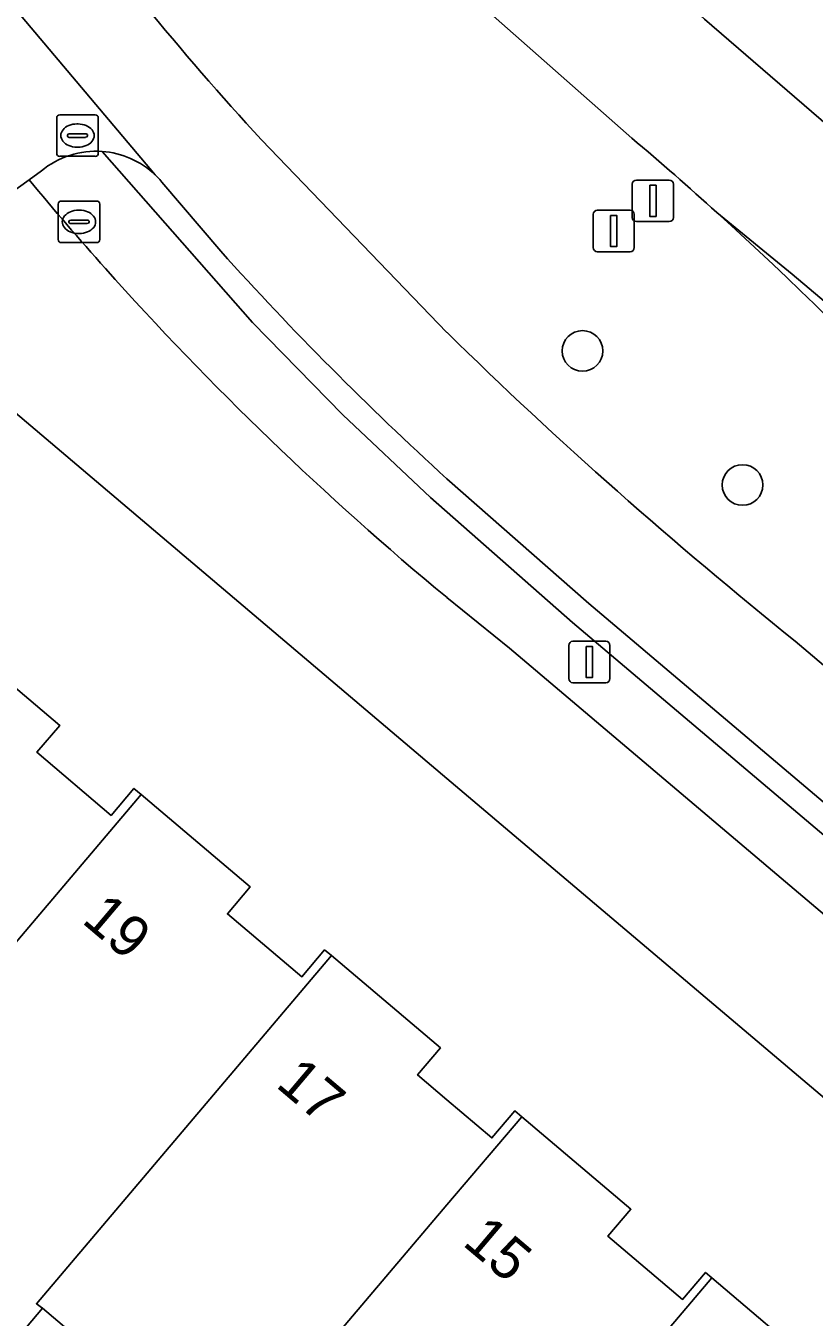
# Model space of a CAD drawing. Extents: x 156412 to 157779, y 382335 to 383768.
# Drawn here: x 156989.86 to 157008.84, y 382838.16 to 382869.24 of the extents above; entities that cross this region are included whole.
import ezdxf

# ---------------------------------------------------------------- set-up
doc = ezdxf.new("R2010")
doc.units = 0
for name, color, linetype in [('IMGEO_Berm_groen', 7, 'Continuous'), ('IMGEO_Boom', 7, 'Continuous'), ('IMGEO_Erf', 7, 'Continuous'), ('IMGEO_Fietspad_gesloten', 7, 'Continuous'), ('IMGEO_Groenvoorziening', 7, 'Continuous'), ('IMGEO_Haag', 7, 'Continuous'), ('IMGEO_Lichtmast', 7, 'Continuous'), ('IMGEO_Pand', 7, 'Continuous'), ('IMGEO_Pand_nummerreeks', 7, 'Continuous'), ('IMGEO_Rijbaan_regionaal_gesloten', 7, 'Continuous'), ('IMGEO_Rioolput', 7, 'Continuous'), ('IMGEO_Verkeersbordpaal', 7, 'Continuous'), ('IMGEO_Voetpad_open', 7, 'Continuous')]:
    doc.layers.add(name, color=color, linetype=linetype)

msp = doc.modelspace()

# ---------------------------------------------------------------- linework, layer by layer
at = {"layer": 'IMGEO_Berm_groen'}
for points in [[(157004.449, 382866.535), (157000.639, 382869.902)], [(156995.532, 382866.494), (157000, 382861.855)], [(157003.022, 382854.879), (156999.599, 382857.889), (156997.496, 382859.874), (156995.317, 382862.098), (156991.703, 382866.215)], [(156990.239, 382865.747), (156989.942, 382865.533)], [(157000, 382855.475), (157001.505, 382854.26), (157026.185, 382833.362), (157021.741, 382839.034), (157003.022, 382854.879)], [(157008.381, 382854.428), (157029.109, 382836.876), (157023.909, 382845.783)]]:
    msp.add_lwpolyline(points, dxfattribs=at)
for centre, radius, start, end in [((157052.723, 382918.878), 77.555, 209.71967, 222.48797), ((156951.788, 382804.343), 81.493, 47.83263, 49.74397), ((156991.556, 382864.151), 2.069, 85.925, 129.5303), ((157046.521, 382912.357), 73.441, 219.61068, 221.80815), ((156949.459, 382801.656), 85.048, 37.97711, 47.88442), ((157048.582, 382914.11), 76.146, 221.75797, 230.35703), ((157079.4, 382943.011), 113.537, 225.62684, 231.28029)]:
    msp.add_arc(centre, radius, start, end, dxfattribs=at)
at = {"layer": 'IMGEO_Boom'}
for centre in [(157003.261, 382861.414), (157007.113, 382858.187)]:
    msp.add_circle(centre, 0.489, dxfattribs=at)
at = {"layer": 'IMGEO_Erf'}
msp.add_lwpolyline([(157000, 382851.126), (156988.027, 382861.266), (156983.836, 382860.322), (156945.662, 382851.459), (156966.822, 382759.288), (156968.984, 382750), (156976.601, 382717.276), (157000, 382744.884), (157004.336, 382750), (157004.803, 382750.551), (157041.321, 382793.644), (157052.477, 382806.707), (157037.953, 382818.984), (157034.372, 382822.017), (157032.691, 382823.44)], close=True, dxfattribs=at)
for points in [[(156988.066, 382854.616), (156990.682, 382852.401), (156990.132, 382851.753), (156991.917, 382850.235), (156992.466, 382850.883), (156992.642, 382850.735), (156995.264, 382848.511), (156994.714, 382847.863), (156996.507, 382846.349), (156997.056, 382846.998), (156997.221, 382846.858), (156999.843, 382844.638), (156999.294, 382843.989), (157000, 382843.389), (157001.081, 382842.471), (157001.63, 382843.12), (157001.798, 382842.978), (157004.424, 382840.754), (157003.874, 382840.105), (157005.67, 382838.585), (157006.221, 382839.233), (157006.377, 382839.1), (157008.997, 382836.873)], [(157011.713, 382817.561), (157006.989, 382821.57), (157008.283, 382823.095), (157004.004, 382826.72), (157002.709, 382825.196), (157000, 382827.497), (156997.834, 382829.337), (156999.12, 382830.85), (156994.703, 382834.611), (156990.265, 382838.372), (156988.973, 382836.846), (156984.103, 382840.969), (156985.39, 382842.489), (156981.86, 382845.483), (156978.289, 382841.269), (156976.092, 382838.674), (156974.35, 382840.15), (156976.547, 382842.745), (156978.826, 382845.436), (156974.937, 382848.74), (156976.048, 382850.048), (156969.215, 382848.468)]]:
    msp.add_lwpolyline(points, dxfattribs=at)
at = {"layer": 'IMGEO_Fietspad_gesloten'}
for points in [[(156992.974, 382865.655), (156988.864, 382870.528)], [(156988.864, 382870.528), (156992.974, 382865.655), (156993.032, 382865.598), (156993.087, 382865.539), (156993.14, 382865.477), (156994.554, 382863.812)], [(157000, 382861.855), (156995.532, 382866.494)], [(156988.655, 382864.607), (156989.942, 382865.533)], [(156989.942, 382865.533), (156990.239, 382865.747)], [(157000, 382858.335), (157003.414, 382855.333), (157019.915, 382841.365), (157038.617, 382825.406), (157038.906, 382825.171), (157041.277, 382823.243), (157041.521, 382822.993), (157053.712, 382810.538), (157053.424, 382809.597), (157055.088, 382808.988), (157054.971, 382808.492)], [(157057.235, 382812.195), (157055.114, 382814.174), (157048.576, 382819.923), (157045.729, 382822.419), (157042.831, 382825.236), (157040.215, 382827.472), (157029.109, 382836.876), (157008.381, 382854.428)]]:
    msp.add_lwpolyline(points, dxfattribs=at)
for centre, radius, start, end in [((157052.723, 382918.878), 77.555, 209.71967, 222.48797), ((156991.556, 382864.151), 2.069, 85.925, 129.5303), ((156991.554, 382864.154), 2.066, 46.5793, 85.8643), ((157052.844, 382916.326), 78.457, 222.01598, 227.65881), ((157079.4, 382943.011), 113.537, 225.62684, 231.28029)]:
    msp.add_arc(centre, radius, start, end, dxfattribs=at)
at = {"layer": 'IMGEO_Groenvoorziening'}
for points in [[(156991.703, 382866.215), (156995.317, 382862.098), (156997.496, 382859.874), (156999.599, 382857.889), (157003.022, 382854.879), (157021.741, 382839.034), (157019.915, 382841.365), (157003.414, 382855.333)], [(156994.554, 382863.812), (156993.14, 382865.477), (156993.087, 382865.539), (156993.032, 382865.598), (156992.974, 382865.655)], [(157003.414, 382855.333), (157000, 382858.335)]]:
    msp.add_lwpolyline(points, dxfattribs=at)
for centre, radius, start, end in [((156991.554, 382864.154), 2.066, 46.5793, 85.8643), ((157052.844, 382916.326), 78.457, 222.01598, 227.65881)]:
    msp.add_arc(centre, radius, start, end, dxfattribs=at)
at = {"layer": 'IMGEO_Haag'}
for points in [[(156991.703, 382866.215), (156995.317, 382862.098), (156997.496, 382859.874), (156999.599, 382857.889), (157003.022, 382854.879), (157021.741, 382839.034), (157019.915, 382841.365), (157003.414, 382855.333)], [(156994.554, 382863.812), (156993.14, 382865.477), (156993.087, 382865.539), (156993.032, 382865.598), (156992.974, 382865.655)], [(157003.414, 382855.333), (157000, 382858.335)]]:
    msp.add_lwpolyline(points, dxfattribs=at)
for centre, radius, start, end in [((156991.554, 382864.154), 2.066, 46.5793, 85.8643), ((157052.844, 382916.326), 78.457, 222.01598, 227.65881)]:
    msp.add_arc(centre, radius, start, end, dxfattribs=at)
at = {"layer": 'IMGEO_Lichtmast'}
for p, q in [((157003.031, 382854.426), (157003.821, 382854.426)), ((157003.821, 382854.426), (157003.031, 382854.426)), ((157002.931, 382853.526), (157002.931, 382854.326)), ((157002.931, 382854.326), (157002.931, 382853.526)), ((157003.921, 382854.326), (157003.921, 382853.526)), ((157003.921, 382853.526), (157003.921, 382854.326)), ((157003.821, 382853.426), (157003.031, 382853.426)), ((157003.031, 382853.426), (157003.821, 382853.426))]:
    msp.add_line(p, q, dxfattribs=at)
msp.add_lwpolyline([(157003.351, 382854.301), (157003.501, 382854.301), (157003.501, 382853.551), (157003.351, 382853.551), (157003.351, 382854.301)], dxfattribs=at)
for centre, start, end in [((157003.031, 382854.326), 90, 180), ((157003.031, 382854.326), 90, 180), ((157003.821, 382854.326), 0, 90), ((157003.821, 382854.326), 360, 90), ((157003.031, 382853.526), 180, 270), ((157003.031, 382853.526), 180, 270), ((157003.821, 382853.526), 270, 0), ((157003.821, 382853.526), 270, 0)]:
    msp.add_arc(centre, 0.1, start, end, dxfattribs=at)
at = {"layer": 'IMGEO_Pand'}
for points in [[(156992.642, 382850.735), (156992.466, 382850.883), (156991.917, 382850.235), (156990.132, 382851.753), (156990.682, 382852.401), (156988.066, 382854.616), (156980.965, 382846.24), (156981.115, 382846.115), (156981.86, 382845.483), (156985.39, 382842.489), (156985.542, 382842.36)], [(156990.265, 382838.372), (156990.119, 382838.48), (156997.221, 382846.858), (156997.056, 382846.998), (156996.507, 382846.349), (156994.714, 382847.863), (156995.264, 382848.511), (156992.642, 382850.735), (156985.542, 382842.36), (156985.39, 382842.489), (156984.103, 382840.969), (156988.973, 382836.846)], [(156990.265, 382838.372), (156994.703, 382834.611), (157000, 382840.858), (157001.798, 382842.978), (157001.63, 382843.12), (157001.081, 382842.471), (157000, 382843.389), (156999.294, 382843.989), (156999.843, 382844.638), (156997.221, 382846.858), (156990.119, 382838.48)], [(157006.377, 382839.1), (157006.221, 382839.233), (157005.67, 382838.585), (157003.874, 382840.105), (157004.424, 382840.754), (157001.798, 382842.978), (157000, 382840.858), (156994.703, 382834.611), (156999.12, 382830.85), (156999.273, 382830.721), (157000, 382831.578)], [(157006.377, 382839.1), (157000, 382831.578), (156999.273, 382830.721), (156999.12, 382830.85), (156997.834, 382829.337), (157000, 382827.497), (157002.709, 382825.196), (157004.004, 382826.72), (157003.849, 382826.841), (157010.952, 382835.219), (157010.786, 382835.36), (157010.236, 382834.712), (157008.447, 382836.225), (157008.997, 382836.873)]]:
    msp.add_lwpolyline(points, close=True, dxfattribs=at)
at = {"layer": 'IMGEO_Rijbaan_regionaal_gesloten'}
for points in [[(157006.494, 382864.744), (157008.308, 382863.258), (157050.347, 382827.796), (157052.459, 382830.26), (157024.101, 382854.154), (157015.155, 382861.664), (157012.124, 382864.283), (157009.183, 382866.824), (157006.198, 382869.403), (157003.289, 382872.069), (157000.491, 382874.849), (156997.855, 382877.785), (156995.385, 382880.96), (156993.19, 382884.173), (156991.108, 382887.606), (156989.243, 382891.043), (156987.542, 382894.682), (156986.045, 382898.331), (156984.778, 382902.066), (156983.759, 382905.876), (156981.738, 382914.026), (156977.939, 382930.341), (156974.563, 382944.839), (156971.703, 382954.608)], [(157000.639, 382869.902), (157004.449, 382866.535)], [(157006.198, 382869.403), (157009.183, 382866.824), (157012.124, 382864.283), (157015.155, 382861.664), (157024.101, 382854.154), (157052.459, 382830.26), (157054.556, 382832.705), (157010.813, 382869.742)], [(157025.031, 382844.86), (157048.179, 382825.267), (157050.347, 382827.796), (157008.308, 382863.258), (157006.494, 382864.744)]]:
    msp.add_lwpolyline(points, dxfattribs=at)
for centre, radius, start, end in [((156951.788, 382804.343), 81.493, 47.83263, 49.74397), ((156949.459, 382801.656), 85.048, 37.97711, 47.88442)]:
    msp.add_arc(centre, radius, start, end, dxfattribs=at)
at = {"layer": 'IMGEO_Rioolput'}
for p, q in [((156990.682, 382867.098), (156991.534, 382867.098)), ((156990.607, 382866.172), (156990.607, 382867.024)), ((156991.095, 382866.878), (156991.12, 382866.878)), ((156991.608, 382867.024), (156991.608, 382866.172)), ((156990.866, 382866.592), (156990.866, 382866.604)), ((156991.304, 382866.555), (156990.906, 382866.555)), ((156990.909, 382866.641), (156991.307, 382866.641)), ((156991.35, 382866.604), (156991.35, 382866.592)), ((156991.118, 382866.318), (156991.093, 382866.318)), ((156991.534, 382866.098), (156990.682, 382866.098)), ((156990.643, 382864.095), (156990.643, 382864.947)), ((156990.718, 382865.021), (156991.57, 382865.021)), ((156991.644, 382864.947), (156991.644, 382864.095)), ((156991.131, 382864.801), (156991.156, 382864.801)), ((156990.902, 382864.515), (156990.902, 382864.527)), ((156991.34, 382864.478), (156990.942, 382864.478)), ((156990.945, 382864.564), (156991.343, 382864.564)), ((156991.386, 382864.527), (156991.386, 382864.515)), ((156991.57, 382864.021), (156990.718, 382864.021)), ((156991.154, 382864.241), (156991.129, 382864.241))]:
    msp.add_line(p, q, dxfattribs=at)
for points in [[(156990.682, 382867.098), (156991.534, 382867.098)], [(156990.607, 382866.172), (156990.607, 382867.024)], [(156991.608, 382867.024), (156991.608, 382866.172)], [(156991.534, 382866.098), (156990.682, 382866.098)], [(156990.643, 382864.095), (156990.643, 382864.947)], [(156990.718, 382865.021), (156991.57, 382865.021)], [(156991.644, 382864.947), (156991.644, 382864.095)], [(156991.57, 382864.021), (156990.718, 382864.021)]]:
    msp.add_lwpolyline(points, dxfattribs=at)
for centre, radius, start, end in [((156990.684, 382867.022), 0.0765, 91.552, 178.448), ((156990.684, 382867.022), 0.0765, 91.552, 178.448), ((156991.532, 382867.022), 0.0765, 1.552, 88.448), ((156991.532, 382867.022), 0.0765, 1.552, 88.448), ((156990.906, 382866.601), 0.0403, 85.8775, 175.7526), ((156990.903, 382866.591), 0.0366, 178.938, 274.7102), ((156991.307, 382866.598), 0.043, 264.8664, 352.4533), ((156991.311, 382866.603), 0.0386, 1.7309, 96.639), ((156990.684, 382866.174), 0.0765, 181.552, 268.448), ((156990.684, 382866.174), 0.0765, 181.552, 268.448), ((156991.532, 382866.174), 0.0765, 271.552, 358.448), ((156991.532, 382866.174), 0.0765, 271.552, 358.448), ((156990.72, 382864.945), 0.0765, 91.552, 178.448), ((156990.72, 382864.945), 0.0765, 91.552, 178.448), ((156991.568, 382864.945), 0.0765, 1.552, 88.448), ((156991.568, 382864.945), 0.0765, 1.552, 88.448), ((156990.942, 382864.524), 0.0403, 85.8775, 175.7526), ((156990.939, 382864.514), 0.0366, 178.938, 274.7102), ((156991.343, 382864.521), 0.043, 264.8664, 352.4533), ((156991.347, 382864.526), 0.0386, 1.7309, 96.639), ((156990.72, 382864.097), 0.0765, 181.552, 268.448), ((156990.72, 382864.097), 0.0765, 181.552, 268.448), ((156991.568, 382864.097), 0.0765, 271.552, 358.448), ((156991.568, 382864.097), 0.0765, 271.552, 358.448)]:
    msp.add_arc(centre, radius, start, end, dxfattribs=at)
for centre, major_axis, ratio, start_param, end_param in [((156991.094, 382866.598), (-0.387, 0.002), 0.722429, 4.712389, 7.853982), ((156991.119, 382866.598), (-0.39, 0.002), 0.717154, 1.570796, 4.712389), ((156991.13, 382864.521), (-0.387, 0.002), 0.722429, 4.712389, 7.853982), ((156991.155, 382864.521), (-0.39, 0.002), 0.717154, 1.570796, 4.712389)]:
    msp.add_ellipse(centre, major_axis=major_axis, ratio=ratio, start_param=start_param, end_param=end_param, dxfattribs=at)
at = {"layer": 'IMGEO_Verkeersbordpaal'}
for p, q in [((157004.46, 382864.627), (157004.46, 382865.427)), ((157004.46, 382865.427), (157004.46, 382864.627)), ((157004.56, 382865.527), (157005.35, 382865.527)), ((157005.35, 382865.527), (157004.56, 382865.527)), ((157005.45, 382865.427), (157005.45, 382864.627)), ((157005.45, 382864.627), (157005.45, 382865.427)), ((157003.517, 382863.902), (157003.517, 382864.702)), ((157003.517, 382864.702), (157003.517, 382863.902)), ((157003.617, 382864.802), (157004.407, 382864.802)), ((157004.407, 382864.802), (157003.617, 382864.802)), ((157004.507, 382864.702), (157004.507, 382863.902)), ((157004.507, 382863.902), (157004.507, 382864.702)), ((157005.35, 382864.527), (157004.56, 382864.527)), ((157004.56, 382864.527), (157005.35, 382864.527)), ((157004.407, 382863.802), (157003.617, 382863.802)), ((157003.617, 382863.802), (157004.407, 382863.802))]:
    msp.add_line(p, q, dxfattribs=at)
for points in [[(157004.88, 382865.402), (157005.03, 382865.402), (157005.03, 382864.652), (157004.88, 382864.652), (157004.88, 382865.402)], [(157003.937, 382864.677), (157004.087, 382864.677), (157004.087, 382863.927), (157003.937, 382863.927), (157003.937, 382864.677)]]:
    msp.add_lwpolyline(points, dxfattribs=at)
for centre, start, end in [((157004.56, 382865.427), 90, 180), ((157004.56, 382865.427), 90, 180), ((157005.35, 382865.427), 0, 90), ((157005.35, 382865.427), 360, 90), ((157003.617, 382864.702), 90, 180), ((157003.617, 382864.702), 90, 180), ((157004.407, 382864.702), 0, 90), ((157004.407, 382864.702), 360, 90), ((157004.56, 382864.627), 180, 270), ((157004.56, 382864.627), 180, 270), ((157005.35, 382864.627), 270, 0), ((157005.35, 382864.627), 270, 0), ((157003.617, 382863.902), 180, 270), ((157003.617, 382863.902), 180, 270), ((157004.407, 382863.902), 270, 0), ((157004.407, 382863.902), 270, 0)]:
    msp.add_arc(centre, 0.1, start, end, dxfattribs=at)
at = {"layer": 'IMGEO_Voetpad_open'}
for points in [[(156989.942, 382865.533), (156988.655, 382864.607)], [(156985.884, 382863.097), (156988.027, 382861.266), (157000, 382851.126), (157032.691, 382823.44), (157034.372, 382822.017), (157037.953, 382818.984), (157052.477, 382806.707), (157052.522, 382806.841), (157053.424, 382809.597), (157053.712, 382810.538), (157041.521, 382822.993), (157041.277, 382823.243), (157038.906, 382825.171), (157038.578, 382824.782), (157037.636, 382823.666), (157026.185, 382833.362), (157001.505, 382854.26), (157000, 382855.475)]]:
    msp.add_lwpolyline(points, dxfattribs=at)
for centre, radius, start, end in [((157046.521, 382912.357), 73.441, 219.61068, 221.80815), ((157048.582, 382914.11), 76.146, 221.75797, 230.35703)]:
    msp.add_arc(centre, radius, start, end, dxfattribs=at)

# ---------------------------------------------------------------- texts
at = {"layer": 'IMGEO_Pand_nummerreeks'}
for s, rotation, p in [('19', 319.7006, (156991.183, 382847.671)), ('17', 319.7439, (156995.851, 382843.72)), ('15', 319.736, (157000.346, 382839.91))]:
    msp.add_text(s, height=1, rotation=rotation, dxfattribs=at).set_placement(p)

doc.saveas('drawing.dxf')
